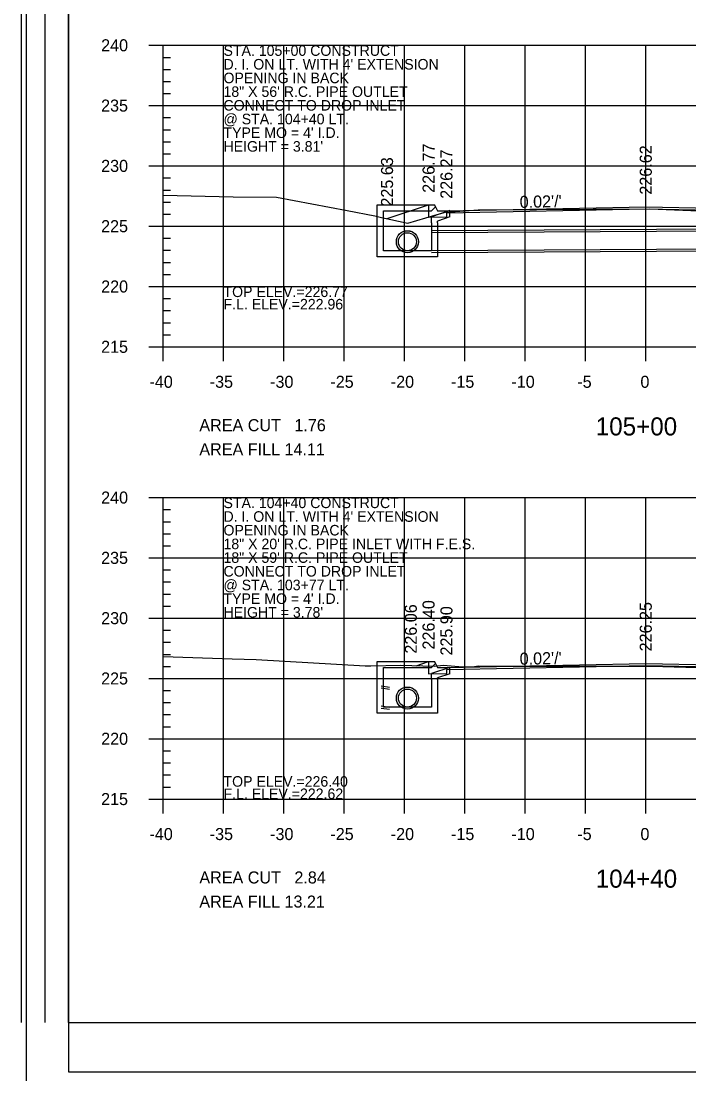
# Model space of a CAD drawing. Extents: x 1367903 to 1373764, y 376865 to 382130.
# Drawn here: x 1370927.2 to 1371037.9, y 377279.1 to 377454.8 of the extents above; entities that cross this region are included whole.
import ezdxf

# ---------------------------------------------------------------- set-up
doc = ezdxf.new("R2010")
doc.units = 0
for name, color, linetype in [('R_Axis', 7, 'Continuous'), ('R_Axis Annot', 7, 'Continuous'), ('R_Border', 7, 'Continuous'), ('R_Border PE', 7, 'Continuous'), ('R_Draft', 7, 'Continuous'), ('R_Exist Surface', 7, 'Continuous'), ('R_Fin Surface', 7, 'Continuous'), ('R_Fin Surface Annot', 7, 'Continuous'), ('R_Grid', 7, 'Continuous'), ('R_Water', 7, 'Continuous'), ('R_Water Annot', 7, 'Continuous')]:
    doc.layers.add(name, color=color, linetype=linetype)

msp = doc.modelspace()

# ---------------------------------------------------------------- linework, layer by layer
for p, q in [((1370986.25, 377424.38), (1370995.75, 377424.38)), ((1370986.25, 377421.38), (1370986.25, 377424.38)), ((1370995.91, 377424.05), (1370995.75, 377424.38)), ((1370987.25, 377421.38), (1370987.25, 377423.38)), ((1370987.25, 377423.38), (1370995.25, 377423.38)), ((1370995.91, 377424.05), (1370995.25, 377423.38)), ((1370998.25, 377423.42), (1370995.25, 377422.38)), ((1370995.25, 377421.38), (1370995.25, 377422.38)), ((1370998.25, 377422.37), (1370996.25, 377421.67)), ((1370996.25, 377421.38), (1370996.25, 377421.67)), ((1370986.25, 377348.64), (1370995.75, 377348.64)), ((1370986.25, 377345.64), (1370986.25, 377348.64)), ((1370987.25, 377345.64), (1370987.25, 377347.64)), ((1370987.25, 377347.64), (1370995.25, 377347.64)), ((1370995.91, 377348.31), (1370995.25, 377347.64)), ((1370998.25, 377347.68), (1370995.25, 377346.64)), ((1370995.91, 377348.31), (1370995.75, 377348.64)), ((1370995.25, 377345.64), (1370995.25, 377346.64)), ((1370998.25, 377346.62), (1370996.25, 377345.93)), ((1370996.25, 377345.64), (1370996.25, 377345.93))]:
    msp.add_line(p, q)
for points in [[(1370994.75, 377424.38), (1370994.75, 377423.72), (1370994.75, 377423.72), (1370994.75, 377422.35), (1370997.75, 377422.41), (1370997.75, 377423.08), (1371030.75, 377423.74), (1371063.75, 377423.08), (1371063.75, 377422.41), (1371066.75, 377422.35), (1371066.75, 377423.8), (1371080.75, 377424.08), (1371080.75, 377424.66)], [(1370998.25, 377422.37), (1370998.25, 377423.42)], [(1370994.75, 377348.64), (1370994.75, 377347.97), (1370994.75, 377347.97), (1370994.75, 377346.61), (1370997.75, 377346.67), (1370997.75, 377347.34), (1371030.75, 377348), (1371063.75, 377347.34), (1371063.75, 377346.67), (1371066.75, 377346.61), (1371066.75, 377348.05), (1371080.75, 377348.33), (1371080.75, 377348.92)], [(1370998.25, 377346.62), (1370998.25, 377347.68)]]:
    msp.add_lwpolyline(points)
at = {"layer": 'R_Axis'}
for p, q in [((1370948.35, 377450.84), (1370953.15, 377450.84)), ((1370950.75, 377400.84), (1370950.75, 377450.84)), ((1370950.75, 377448.84), (1370951.95, 377448.84)), ((1370950.75, 377446.84), (1370951.95, 377446.84)), ((1370950.75, 377444.84), (1370951.95, 377444.84)), ((1370950.75, 377442.84), (1370951.95, 377442.84)), ((1370948.35, 377440.84), (1370953.15, 377440.84)), ((1370950.75, 377438.84), (1370951.95, 377438.84)), ((1370950.75, 377436.84), (1370951.95, 377436.84)), ((1370950.75, 377434.84), (1370951.95, 377434.84)), ((1370950.75, 377432.84), (1370951.95, 377432.84)), ((1370948.35, 377430.84), (1370953.15, 377430.84)), ((1370950.75, 377428.84), (1370951.95, 377428.84)), ((1370950.75, 377426.84), (1370951.95, 377426.84)), ((1370950.75, 377424.84), (1370951.95, 377424.84)), ((1370950.75, 377422.84), (1370951.95, 377422.84)), ((1370948.35, 377420.84), (1370953.15, 377420.84)), ((1370950.75, 377418.84), (1370951.95, 377418.84)), ((1370950.75, 377416.84), (1370951.95, 377416.84)), ((1370950.75, 377414.84), (1370951.95, 377414.84)), ((1370950.75, 377412.84), (1370951.95, 377412.84)), ((1370948.35, 377410.84), (1370953.15, 377410.84)), ((1370950.75, 377408.84), (1370951.95, 377408.84)), ((1370950.75, 377406.84), (1370951.95, 377406.84)), ((1370950.75, 377404.84), (1370951.95, 377404.84)), ((1370950.75, 377398.44), (1370950.75, 377403.24)), ((1370950.75, 377402.84), (1370951.95, 377402.84)), ((1370960.75, 377398.44), (1370960.75, 377403.24)), ((1370970.75, 377398.44), (1370970.75, 377403.24)), ((1370980.75, 377398.44), (1370980.75, 377403.24)), ((1370990.75, 377398.44), (1370990.75, 377403.24)), ((1371000.75, 377398.44), (1371000.75, 377403.24)), ((1371010.75, 377398.44), (1371010.75, 377403.24)), ((1371020.75, 377398.44), (1371020.75, 377403.24)), ((1371030.75, 377398.44), (1371030.75, 377403.24)), ((1370948.35, 377400.84), (1370953.15, 377400.84)), ((1370950.75, 377400.84), (1371110.75, 377400.84)), ((1370948.35, 377375.84), (1370953.15, 377375.84)), ((1370950.75, 377325.84), (1370950.75, 377375.84)), ((1370950.75, 377373.84), (1370951.95, 377373.84)), ((1370950.75, 377371.84), (1370951.95, 377371.84)), ((1370950.75, 377369.84), (1370951.95, 377369.84)), ((1370950.75, 377367.84), (1370951.95, 377367.84)), ((1370948.35, 377365.84), (1370953.15, 377365.84)), ((1370950.75, 377363.84), (1370951.95, 377363.84)), ((1370950.75, 377361.84), (1370951.95, 377361.84)), ((1370950.75, 377359.84), (1370951.95, 377359.84)), ((1370950.75, 377357.84), (1370951.95, 377357.84)), ((1370948.35, 377355.84), (1370953.15, 377355.84)), ((1370950.75, 377353.84), (1370951.95, 377353.84)), ((1370950.75, 377351.84), (1370951.95, 377351.84)), ((1370950.75, 377349.84), (1370951.95, 377349.84)), ((1370950.75, 377347.84), (1370951.95, 377347.84)), ((1370948.35, 377345.84), (1370953.15, 377345.84)), ((1370950.75, 377343.84), (1370951.95, 377343.84)), ((1370950.75, 377341.84), (1370951.95, 377341.84)), ((1370950.75, 377339.84), (1370951.95, 377339.84)), ((1370950.75, 377337.84), (1370951.95, 377337.84)), ((1370948.35, 377335.84), (1370953.15, 377335.84)), ((1370950.75, 377333.84), (1370951.95, 377333.84)), ((1370950.75, 377331.84), (1370951.95, 377331.84)), ((1370950.75, 377329.84), (1370951.95, 377329.84)), ((1370950.75, 377323.44), (1370950.75, 377328.24)), ((1370950.75, 377327.84), (1370951.95, 377327.84)), ((1370960.75, 377323.44), (1370960.75, 377328.24)), ((1370970.75, 377323.44), (1370970.75, 377328.24)), ((1370980.75, 377323.44), (1370980.75, 377328.24)), ((1370990.75, 377323.44), (1370990.75, 377328.24)), ((1371000.75, 377323.44), (1371000.75, 377328.24)), ((1371010.75, 377323.44), (1371010.75, 377328.24)), ((1371020.75, 377323.44), (1371020.75, 377328.24)), ((1371030.75, 377323.44), (1371030.75, 377328.24)), ((1370948.35, 377325.84), (1370953.15, 377325.84)), ((1370950.75, 377325.84), (1371110.75, 377325.84))]:
    msp.add_line(p, q, dxfattribs=at)
at = {"layer": 'R_Border'}
for p, q in [((1370928.02, 377620.35), (1370928.02, 377279.12)), ((1370935.05, 377611.47), (1370935.05, 377280.59)), ((1370935.05, 377280.59), (1371139.37, 377280.59))]:
    msp.add_line(p, q, dxfattribs=at)
at = {"layer": 'R_Border PE'}
for p, q in [((1370927.22, 377610.76), (1370927.22, 377288.8)), ((1370931.13, 377610.76), (1370931.13, 377288.8)), ((1370935.05, 377288.8), (1370935.05, 377603.25)), ((1370935.05, 377288.8), (1371139.37, 377288.8))]:
    msp.add_line(p, q, dxfattribs=at)
at = {"layer": 'R_Exist Surface'}
for points in [[(1370950.75, 377426), (1370962.36, 377425.7), (1370969.54, 377425.63), (1370981.27, 377423.45), (1370985.86, 377422.58), (1370986.97, 377422.28), (1370991.32, 377421.34), (1370995.8, 377422.68), (1370997.54, 377423.14), (1371000.78, 377423.41), (1371002.95, 377423.57), (1371012.64, 377423.59), (1371031.45, 377423.71), (1371043.7, 377423.22)], [(1370950.75, 377349.49), (1370962.18, 377349.07), (1370966.18, 377348.98), (1370984.26, 377347.92), (1370985.15, 377347.94), (1370990.11, 377348.02), (1370995.67, 377347.89), (1370997.24, 377348.04), (1371000.37, 377347.75), (1371002.04, 377347.79), (1371003.04, 377347.91), (1371008.22, 377347.9), (1371031.66, 377347.86), (1371041.23, 377347.62)]]:
    msp.add_lwpolyline(points, dxfattribs=at)
at = {"layer": 'R_Fin Surface'}
for points in [[(1370987.86, 377422.09), (1370994.75, 377424.38), (1370995.75, 377424.38), (1370996.25, 377423.38), (1370997.75, 377423.41), (1371019.75, 377423.85), (1371030.75, 377424.07), (1371041.75, 377423.85), (1371063.75, 377423.41), (1371065.25, 377423.38), (1371065.75, 377424.38), (1371066.75, 377424.38), (1371070.75, 377424.46), (1371080.75, 377424.66), (1371088.41, 377422.11)], [(1370992.71, 377347.96), (1370994.75, 377348.64), (1370995.75, 377348.64), (1370996.25, 377347.64), (1370997.75, 377347.67), (1371019.75, 377348.11), (1371030.75, 377348.33), (1371041.75, 377348.11), (1371063.75, 377347.67), (1371065.25, 377347.64), (1371065.75, 377348.64), (1371066.75, 377348.64), (1371070.75, 377348.72), (1371080.75, 377348.92), (1371089.2, 377346.1)]]:
    msp.add_lwpolyline(points, dxfattribs=at)
at = {"layer": 'R_Grid'}
for p, q in [((1370950.75, 377450.84), (1371110.75, 377450.84)), ((1370950.75, 377400.84), (1370950.75, 377450.84)), ((1370960.75, 377400.84), (1370960.75, 377450.84)), ((1370970.75, 377400.84), (1370970.75, 377450.84)), ((1370980.75, 377400.84), (1370980.75, 377450.84)), ((1370990.75, 377400.84), (1370990.75, 377450.84)), ((1371000.75, 377400.84), (1371000.75, 377450.84)), ((1371010.75, 377400.84), (1371010.75, 377450.84)), ((1371020.75, 377400.84), (1371020.75, 377450.84)), ((1371030.75, 377400.84), (1371030.75, 377450.84)), ((1370950.75, 377440.84), (1371110.75, 377440.84)), ((1370950.75, 377430.84), (1371110.75, 377430.84)), ((1370950.75, 377420.84), (1371110.75, 377420.84)), ((1370950.75, 377410.84), (1371110.75, 377410.84)), ((1370950.75, 377400.84), (1371110.75, 377400.84)), ((1370950.75, 377375.84), (1371110.75, 377375.84)), ((1370950.75, 377325.84), (1370950.75, 377375.84)), ((1370960.75, 377325.84), (1370960.75, 377375.84)), ((1370970.75, 377325.84), (1370970.75, 377375.84)), ((1370980.75, 377325.84), (1370980.75, 377375.84)), ((1370990.75, 377325.84), (1370990.75, 377375.84)), ((1371000.75, 377325.84), (1371000.75, 377375.84)), ((1371010.75, 377325.84), (1371010.75, 377375.84)), ((1371020.75, 377325.84), (1371020.75, 377375.84)), ((1371030.75, 377325.84), (1371030.75, 377375.84)), ((1370950.75, 377365.84), (1371110.75, 377365.84)), ((1370950.75, 377355.84), (1371110.75, 377355.84)), ((1370950.75, 377345.84), (1371110.75, 377345.84)), ((1370950.75, 377335.84), (1371110.75, 377335.84)), ((1370950.75, 377325.84), (1371110.75, 377325.84))]:
    msp.add_line(p, q, dxfattribs=at)
at = {"layer": 'R_Water'}
for p, q in [((1371066.25, 377420.51), (1370995.25, 377420.09)), ((1371066.25, 377420.18), (1370995.25, 377419.76)), ((1371066.25, 377417.18), (1370995.25, 377416.76)), ((1371066.25, 377416.85), (1370995.25, 377416.42)), ((1370986.88, 377344.61), (1370988.29, 377344.41)), ((1370986.88, 377344.28), (1370988.29, 377344.08)), ((1370986.88, 377341.28), (1370988.29, 377341.08)), ((1370986.88, 377340.94), (1370988.29, 377340.74))]:
    msp.add_line(p, q, dxfattribs=at)
for points in [[(1370996.25, 377421.38), (1370996.25, 377415.75), (1370991.25, 377415.75), (1370986.25, 377415.75), (1370986.25, 377421.38)], [(1370995.25, 377421.38), (1370995.25, 377416.75), (1370991.25, 377416.75), (1370987.25, 377416.75), (1370987.25, 377421.38)], [(1370996.25, 377345.64), (1370996.25, 377340.08), (1370991.25, 377340.08), (1370986.25, 377340.08), (1370986.25, 377345.64)], [(1370995.25, 377345.64), (1370995.25, 377341.08), (1370991.25, 377341.08), (1370987.25, 377341.08), (1370987.25, 377345.64)]]:
    msp.add_lwpolyline(points, dxfattribs=at)
for centre, radius in [((1370991.25, 377418.26), 1.83), ((1370991.25, 377418.25), 1.83), ((1370991.25, 377418.26), 1.5), ((1370991.25, 377418.25), 1.5), ((1370991.25, 377342.58), 1.83), ((1370991.25, 377342.58), 1.83), ((1370991.25, 377342.58), 1.5), ((1370991.25, 377342.58), 1.5)]:
    msp.add_circle(centre, radius, dxfattribs=at)

# ---------------------------------------------------------------- texts
at = {"layer": 'R_Axis Annot'}
for s, height, p in [('240', 2, (1370940.47, 377449.84)), ('235', 2, (1370940.46, 377439.84)), ('230', 2, (1370940.47, 377429.84)), ('225', 2, (1370940.46, 377419.84)), ('220', 2, (1370940.47, 377409.84)), ('215', 2, (1370940.46, 377399.84)), ('-40', 2, (1370948.48, 377394.04)), ('-35', 2, (1370958.47, 377394.04)), ('-30', 2, (1370968.48, 377394.04)), ('-25', 2, (1370978.47, 377394.04)), ('-20', 2, (1370988.48, 377394.04)), ('-15', 2, (1370998.47, 377394.04)), ('-10', 2, (1371008.48, 377394.04)), ('-5', 2, (1371019.41, 377394.04)), ('0', 2, (1371029.87, 377394.04)), ('AREA CUT   1.76', 2, (1370956.75, 377386.84)), ('105+00', 3, (1371022.46, 377386.14)), ('AREA FILL 14.11', 2, (1370956.75, 377382.84)), ('240', 2, (1370940.47, 377374.84)), ('235', 2, (1370940.46, 377364.84)), ('230', 2, (1370940.47, 377354.84)), ('225', 2, (1370940.46, 377344.84)), ('220', 2, (1370940.47, 377334.84)), ('215', 2, (1370940.46, 377324.84)), ('-40', 2, (1370948.48, 377319.04)), ('-35', 2, (1370958.47, 377319.04)), ('-30', 2, (1370968.48, 377319.04)), ('-25', 2, (1370978.47, 377319.04)), ('-20', 2, (1370988.48, 377319.04)), ('-15', 2, (1370998.47, 377319.04)), ('-10', 2, (1371008.48, 377319.04)), ('-5', 2, (1371019.41, 377319.04)), ('0', 2, (1371029.87, 377319.04)), ('AREA CUT   2.84', 2, (1370956.75, 377311.84)), ('104+40', 3, (1371022.46, 377311.14)), ('AREA FILL 13.21', 2, (1370956.75, 377307.84))]:
    msp.add_text(s, height=height, dxfattribs=at).set_placement(p)
at = {"layer": 'R_Draft'}
for s, p in [('STA. 105+00 CONSTRUCT', (1370960.75, 377449.09)), ("D. I. ON LT. WITH 4' EXTENSION", (1370960.75, 377446.82)), ('OPENING IN BACK', (1370960.75, 377444.55)), ('18" X 56\' R.C. PIPE OUTLET', (1370960.75, 377442.28)), ('CONNECT TO DROP INLET', (1370960.75, 377440.01)), ('@ STA. 104+40 LT.', (1370960.75, 377437.74)), ("TYPE MO = 4' I.D.", (1370960.75, 377435.47)), ("HEIGHT = 3.81'", (1370960.75, 377433.2)), ('STA. 104+40 CONSTRUCT', (1370960.75, 377374.09)), ("D. I. ON LT. WITH 4' EXTENSION", (1370960.75, 377371.82)), ('OPENING IN BACK', (1370960.75, 377369.55)), ('18" X 20\' R.C. PIPE INLET WITH F.E.S.', (1370960.75, 377367.28)), ('18" X 59\' R.C. PIPE OUTLET', (1370960.75, 377365.01)), ('CONNECT TO DROP INLET', (1370960.75, 377362.74)), ('@ STA. 103+77 LT.', (1370960.75, 377360.47)), ("TYPE MO = 4' I.D.", (1370960.75, 377358.2)), ("HEIGHT = 3.78'", (1370960.75, 377355.94))]:
    msp.add_text(s, height=1.75, dxfattribs=at).set_placement(p)
at = {"layer": 'R_Fin Surface Annot'}
for s, rotation, p in [('226.77', 90, (1370995.75, 377426.38)), ('226.27', 90, (1370998.71, 377425.38)), ('226.62', 90, (1371031.75, 377426.07)), ('225.63', 90, (1370988.86, 377424.09)), ("0.02'/'", 1.1458, (1371009.87, 377423.86)), ('226.06', 90, (1370992.8, 377349.96)), ('226.40', 90, (1370995.75, 377350.64)), ('225.90', 90, (1370998.71, 377349.64)), ('226.25', 90, (1371031.75, 377350.33)), ("0.02'/'", 1.1458, (1371009.87, 377348.11))]:
    msp.add_text(s, height=2, rotation=rotation, dxfattribs=at).set_placement(p)
at = {"layer": 'R_Water Annot'}
for s, p in [('TOP ELEV.=226.77', (1370960.75, 377409.09)), ('F.L. ELEV.=222.96', (1370960.75, 377407.03)), ('TOP ELEV.=226.40', (1370960.75, 377327.89)), ('F.L. ELEV.=222.62', (1370960.75, 377325.84))]:
    msp.add_text(s, height=1.75, dxfattribs=at).set_placement(p)

doc.saveas('drawing.dxf')
